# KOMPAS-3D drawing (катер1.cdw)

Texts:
  ДенисК
  Веек_Compan
  Текст на чертеже
  Размерные надписи
  Шероховатость
  Линия-выноска #1
  Линия-выноска #2
  Линия-выноска #3
  Отклонения формы и база
  Заголовок таблицы
  Ячейка таблицы
  Стрелка вида
  Обозначение изменения
  Фигурная скобка
  Номер узла
  Марка координационной оси
  VRCB
  Выносная надпись
  Обозначение узла
  Марка/позиционное обозначение с линией-выноской
  Марка/позиционное обозначение на линии
  Марка/позиционное обозначение без линии-выноски
Dimensions and other numbers on the sheet: 7; 1; 4; 9; 2; 3; 5; 6; 8; 211,23; 40; 1:1; 0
